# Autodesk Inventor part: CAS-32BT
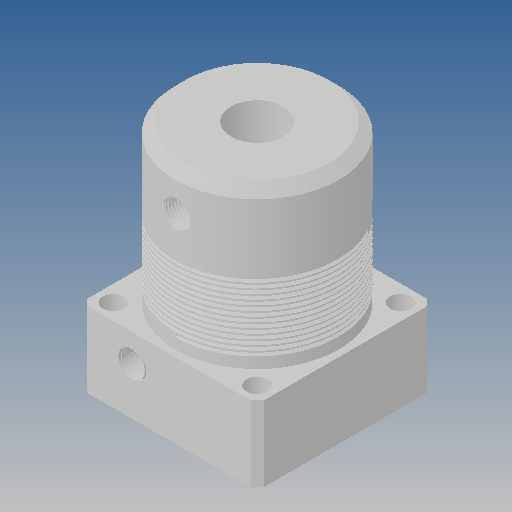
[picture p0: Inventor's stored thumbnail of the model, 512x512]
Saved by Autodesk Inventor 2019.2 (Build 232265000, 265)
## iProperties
Created: 2010-02
Part Number: CAS-32BT
Material: Ogólny
Document SubType Name: Modeling
Designer: CADENGINEERING4
Density: 1 g/cm^3
Appearance: Domyślna
Author: CADENGINEERING4
Revision Number: 2LAST_VERSION
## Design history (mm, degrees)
feature "Baza1"
node "Bryła1"
